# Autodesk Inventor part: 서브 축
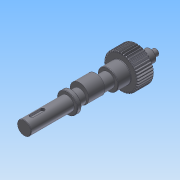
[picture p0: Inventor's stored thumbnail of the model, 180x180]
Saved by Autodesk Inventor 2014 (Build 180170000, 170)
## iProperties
Created: 2016-02
Part Number: 서브 축
Material: 강철, 연강
Document SubType Name: Modeling
Designer: mdu
Categories: <?xml version="1.0" encoding="UTF-16"?> <MemberInstance><Categories><FamilyTemplate><FamilyTemplateParameter ValueType="xs:double" Id="1" ObjectReferenceKey="da
Density: 7.86 g/cm^3
Mass: 504.229 g
Surface Area: 165.255 cm^2
Volume: 64.1512 cm^3
Appearance: 강철
CustomPartVersion: 1
Author: mdu
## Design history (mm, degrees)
sketch "Sketch1"
  geometry: C1 r 21 at (0, 0)
  constraints: 1 centre point
  dimensions: "d0" = 42 diameter of C1 (= da_da)
extrude "Extrusion1" new body sketch "Sketch1" distance "d1" = 20 (= da_b); taper "d2" = 0 deg
workplane "Work Plane2"
feature "피치 지름" dims "d4" = 10, "d5" = 0
workplane "Work Plane8"
workplane "Work Plane9"
chamfer "모따기1" distance "d49" = 1; stored, may be unused: second distance "d50" = 2, angle "d51" = 45 deg
sketch "스케치3"
  geometry: C1 r 12.5 at (0, 0); 1 further point
  constraints: 1 centre point, 1 coincident
  dimensions: "d52" = 25 diameter of C1
extrude "돌출2" join sketch "스케치3" distance "d53" = 16; taper "d54" = 0 deg
sketch "스케치4"
  geometry: C1 r 8.5 at (0, 0); 1 further point
  constraints: 1 centre point, 1 coincident
  dimensions: "d55" = 17 diameter of C1
extrude "돌출3" join sketch "스케치4" distance "d56" = 103; taper "d57" = 0 deg
sketch "스케치5"
  geometry: C1 r 7.5 at (0, 0); 1 further point
  constraints: 1 centre point, 1 coincident
  dimensions: "d62" = 15 diameter of C1
extrude "돌출4" join sketch "스케치5" distance "d63" = 16; taper "d64" = 0 deg
sketch "스케치6"
  geometry: C1 r 4 at (0, 0); 1 further point
  constraints: 1 centre point, 1 coincident
  dimensions: "d65" = 8 diameter of C1
extrude "돌출5" join sketch "스케치6" distance "d66" = 7; taper "d67" = 0 deg
chamfer "모따기2" distance "d58" = 0.5; stored, may be unused: second distance "d59" = 2, angle "d60" = 45 deg
fillet "모깎기1" dims "d61" = 0.5
feature "스퍼 기어" dims "da_b" = 20, "da_d" = 40, "da_aw" = 31, "da_da" = 42, "da_df" = 37.5, "da_dw" = 40, angle "da_beta" = 0 deg, "da_lefttooth" = 0, "da_righttooth" = 0
node "작업 평면11"
sketch "스케치7"
  geometry: C1 r 8.5 at (0, 0) reference; C2 r 11.5 at (0, 3); 1 further point
  constraints: 1 centre point, 1 tangent, 1 vertical alignment
  dimensions: "d71" = 3 distance of C2.centre point (0, 0); "d72" = 23 diameter of C2 (derived)
extrude "돌출6" join sketch "스케치7" stored distance "d73" = 20; taper "d74" = 0 deg
node "작업 평면12"
sketch "스케치8"
  geometry: C1 r 12.5 at (0, 0) reference; 1 further point
extrude "돌출7" join sketch "스케치8" distance "d76" = 5; taper "d77" = 0 deg
chamfer "모따기3" distance "d78" = 0.5; stored, may be unused: second distance "d79" = 2, angle "d80" = 45 deg
sketch "스케치9"
  geometry: L1 (-8.5, 86)-(-8.5, 138.5) reference; L2 (-8, 139)-(8, 139) reference; L3 (0, 0)-(0, 139); L4 (-8.5, 115)-(0, 115); L5 (-8.5, 115)-(-8.5, 113.5); L6 (-7, 115)-(-8.5, 113.5)
  constraints: 8 end point, 4 point on line, 1 midpoint, 1 perpendicular
  dimensions: "d81" = 24 distance between parallel lines of L2 L4; "d82" = 45 deg angle of L6 L5; "d83" = 3 diameter of L5.end L4
revolve "회전1" sketch "스케치9" stored, may be unused: angle "d84" = 90 deg
sketch "스케치10"
  geometry: L1 (-8.5, 113.5)-(-7, 115) reference; L2 (-8.5, 116.5)-(-7, 115) reference; 2 further points
  constraints: 1 coincident
node "작업점1"
node "작업 평면14"
sketch "스케치11"
  geometry: L1 (8.5, 102.5)-(-8.5, 102.5) reference; L2 (0, 102.5)-(0, -36); L3 (-2.5, 93.5)-(-2.5, 80.5); L4 (2.5, 80.5)-(2.5, 93.5); L5 (-8, 103)-(8, 103) reference; A1 r 2.5 centre (0, 93.5) between (2.5, 93.5) and (-2.5, 93.5); A2 r 2.5 centre (0, 80.5) between (-2.5, 80.5) and (2.5, 80.5)
  constraints: 6 end point, 4 point on circle, 4 tangent, 2 centre point, 1 midpoint, 1 parallel, 1 perpendicular, 1 point on line, 1 vertical alignment
  dimensions: "d85" = 7 distance edge to line of A1 L5; "d86" = 18 dimension on A2 A1; "d87" = 5 distance between parallel lines of L3 L4
extrude "돌출8" cut sketch "스케치11" distance "d88" = 3; taper "d89" = 0 deg
body "Solid1"
sketch "Sketch2"
  geometry: C1 r 21 at (0, 0) reference; C2 r 20 at (0, 0)
  constraints: 1 centre point, 1 coincident
  dimensions: "d3" = 40 diameter of C2 (= da_dw)
body "Srf1"
other parameters: "d16" = 31 (= da_aw), "d17" = 0, "d34" = 4.5 deg (computed from da_z), "d39" = 0, "d41" = 0, "d43" = 31 (= da_aw), "d46" = 31 (= da_aw), "d47" = 0, "d48" = 0, "d68" = 25
